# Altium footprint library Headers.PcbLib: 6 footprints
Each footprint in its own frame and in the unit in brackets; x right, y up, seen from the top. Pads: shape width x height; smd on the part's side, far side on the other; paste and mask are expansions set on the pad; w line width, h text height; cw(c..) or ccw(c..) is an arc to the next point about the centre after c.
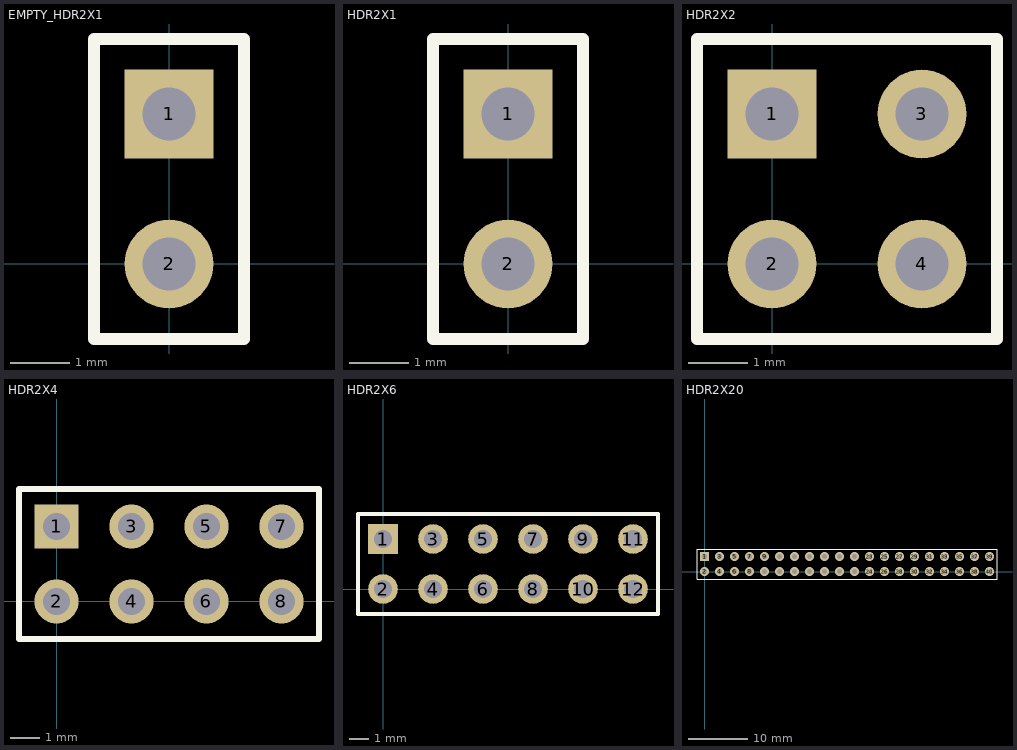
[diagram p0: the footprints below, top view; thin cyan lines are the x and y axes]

## EMPTY_HDR2X1 [mm]
pads (2):
  rect 1.5x1.5 hole 0.9: 1(0,2.54)
  round 1.5 hole 0.9: 2(0,0)
Top Overlay:
  lines w0.2: -1.27,-1.27 -1.27,3.81 1.27,3.81 1.27,-1.27 -1.27,-1.27

## HDR2X1 [mm]
pads (2):
  rect 1.5x1.5 hole 0.9: 1(0,2.54)
  round 1.5 hole 0.9: 2(0,0)
Top Overlay:
  lines w0.2: -1.27,-1.27 1.27,-1.27 1.27,3.81 -1.27,3.81 -1.27,-1.27
3D body "HTSW-102-07-T-S.stp": height 8.38, standoff -2.54, extent -1.245,-1.27 1.245,3.81

## HDR2X2 [mm]
pads (4):
  rect 1.5x1.5 hole 0.9: 1(0,2.54)
  round 1.5 hole 0.9: 2(0,0) 3(2.54,2.54) 4(2.54,0)
Top Overlay:
  lines w0.2: -1.27,-1.27 3.81,-1.27 3.81,3.81 -1.27,3.81 -1.27,-1.27
3D body "TSW-102-07-F-D.stp": height 8.38, standoff -2.54, extent -1.27,-1.27 3.81,3.81

## HDR2X4 [mm]
pads (8):
  rect 1.5x1.5 hole 0.9: 1(0,2.54)
  round 1.5 hole 0.9: 2(0,0) 3(2.54,2.54) 4(2.54,0) 5(5.08,2.54) 6(5.08,0) 7(7.62,2.54) 8(7.62,0)
Top Overlay:
  lines w0.2: -1.27,-1.27 8.89,-1.27 8.89,3.81 -1.27,3.81 -1.27,-1.27
3D body "HTSW-104-07-S-D.stp": height 8.38, standoff -2.54, extent -1.27,-1.244 8.89,3.785

## HDR2X6 [mm]
pads (12):
  rect 1.5x1.5 hole 0.9: 1(0,2.54)
  round 1.5 hole 0.9: 2(0,0) 3(2.54,2.54) 4(2.54,0) 5(5.08,2.54) 6(5.08,0) 7(7.62,2.54) 8(7.62,0) 9(10.16,2.54) 10(10.16,0) 11(12.7,2.54) 12(12.7,0)
Top Overlay:
  lines w0.2: -1.27,-1.27 13.97,-1.27 13.97,3.81 -1.27,3.81 -1.27,-1.27
3D body "TSW-106-07-F-D.stp": height 8.38, standoff -2.54, extent -1.27,-1.27 13.97,3.81

## HDR2X20 [mm]
pads (40):
  rect 1.5x1.5 hole 0.9: 1(0,2.54)
  round 1.5 hole 0.9: 2(0,0) 3(2.54,2.54) 4(2.54,0) 5(5.08,2.54) 6(5.08,0) 7(7.62,2.54) 8(7.62,0) 9(10.16,2.54) 10(10.16,0) 11(12.7,2.54) 12(12.7,0) 13(15.24,2.54) 14(15.24,0) 15(17.78,2.54) 16(17.78,0) 17(20.32,2.54) 18(20.32,0) 19(22.86,2.54) 20(22.86,0) 21(25.4,2.54) 22(25.4,0)
  round 1.524 hole 0.762: 23(27.94,2.54) 24(27.94,0) 25(30.48,2.54) 26(30.48,0) 27(33.02,2.54) 28(33.02,0) 29(35.56,2.54) 30(35.56,0) 31(38.1,2.54) 32(38.1,0) 33(40.64,2.54) 34(40.64,0) 35(43.18,2.54) 36(43.18,0) 37(45.72,2.54) 38(45.72,0) 39(48.26,2.54) 40(48.26,0)
Top Overlay:
  lines w0.2: -1.27,-1.27 49.53,-1.27 49.53,3.81 -1.27,3.81 -1.27,-1.27
3D body "TSW-120-07-F-D.stp": height 8.38, standoff -2.54, extent -1.27,-1.27 49.53,3.81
